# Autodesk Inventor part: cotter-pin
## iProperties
Author: Administrator
Created: 2001-01
Part Number: cotter-pin
Document SubType Name: Modeling
Designer: Administrator
Control State: 0
Master: False
Checked Out: False
PropertySet Name: Design Tracking Control
Shininess: 0.0
PropertySet Name: _Private Model Information
Density: 0.0
Volumn: 0.0
Area: 0.0
PropertySet Name: Model Information
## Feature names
1. Sweep1
